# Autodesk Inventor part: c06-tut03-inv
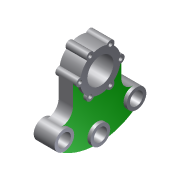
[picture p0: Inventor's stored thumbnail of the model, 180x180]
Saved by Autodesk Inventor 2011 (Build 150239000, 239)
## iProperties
Created: 2010-03
Part Number: c06-tut03-inv
Document SubType Name: Modeling
Designer: CADSoft
Density: 1 g/cm^3
Author: CADSoft
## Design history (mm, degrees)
sketch "Sketch1"
  geometry: 1 further point
sketch "Sketch2"
  geometry: L1 (-37, 0)-(-37, -31.635); L2 (37, 0)-(37, -31.635); A1 r 100 centre (0, 0) between (-64.945, -76.041) and (64.945, -76.041); A2 r 18 centre (-55, -31.635) between (-55.111, -49.635) and (-37, -31.635); A3 r 15 centre (-55.203, -64.635) between (-55.111, -49.635) and (-64.945, -76.041); A4 r 18 centre (55, -31.635) between (37, -31.635) and (55.111, -49.635); A5 r 15 centre (55.203, -64.635) between (64.945, -76.041) and (55.111, -49.635); A6 r 31 centre (0, 0) between (30.419, 5.972) and (-30.419, 5.972); A7 r 6 centre (31, 0) between (37, 0) and (30.419, 5.972); A8 r 6 centre (-31, 0) between (-30.419, 5.972) and (-37, 0); 1 further point
  constraints: 18 point on circle, 8 centre point, 8 tangent, 4 end point, 3 equal radius, 2 coincident, 2 horizontal alignment, 2 vertical, 1 parallel, 1 point on line
  dimensions: "d0" = 100 radius of A1; "d4" = 15 radius of A5; "d5" = 18 radius of A4; "d7" = 81 deg dimension on point (0, 0) A5.centre A3.centre; "d16" = 31 radius of A6; "d17" = 6 radius of A8
extrude "Extrusion1" new body sketch "Sketch2" stored distance "d8" = 22; taper "d9" = 0 deg
sketch "Sketch5"
  geometry: A1 r 6 centre (-31, 0) between (-30.419, 5.972) and (-30.419, -5.972); A2 r 6 centre (-31, 0) between (-30.419, 5.972) and (-37, 0) reference; A3 r 6 centre (-15.5, -26.847) between (-20.381, -23.358) and (-10.038, -29.33); A4 r 6 centre (15.5, -26.847) between (10.038, -29.33) and (20.381, -23.358); A5 r 6 centre (31, 0) between (30.419, -5.972) and (30.419, 5.972); A6 r 6 centre (15.5, 26.847) between (20.381, 23.358) and (10.038, 29.33); A7 r 6 centre (-15.5, 26.847) between (-10.038, 29.33) and (-20.381, 23.358); A8 r 31 centre (0, 0) between (10.038, 29.33) and (-10.038, 29.33); A9 r 31 centre (0, 0) between (30.419, 5.972) and (20.381, 23.358); A10 r 31 centre (0, 0) between (20.381, -23.358) and (30.419, -5.972); A11 r 31 centre (0, 0) between (-20.381, 23.358) and (-30.419, 5.972); A12 r 31 centre (0, 0) between (-30.419, -5.972) and (-20.381, -23.358); A13 r 31 centre (0, 0) between (-10.038, -29.33) and (10.038, -29.33); 1 further point
  constraints: 26 point on circle, 12 centre point, 1 coincident, 1 concentric
extrude "Extrusion2" join sketch "Sketch5" stored distance "d19" = 32; taper "d20" = 0 deg
hole "Hole1" diameter "d23" = 6; stored, may be unused: countersink angle "d27" = 90 deg, drill point angle "d29" = 118 deg; dims "d21" = 10, "d22" = 10, "d24" = 6, "d25" = 4, "d26" = 2, "d28" = 8
pattern_circular "Circular Pattern1" dims angle "d31" = 360 deg
sketch "Sketch6"
  geometry: C1 r 15 at (-55.203, -64.635); A1 r 15 centre (-55.203, -64.635) between (-55.111, -49.635) and (-64.945, -76.041) reference; 1 further point
  constraints: 1 centre point, 1 concentric
  dimensions: "d33" = 30 diameter of C1
extrude "Extrusion3" join sketch "Sketch6" stored distance "d34" = 32; taper "d35" = 0 deg
hole "Hole2" diameter "d38" = 20; stored, may be unused: countersink angle "d42" = 90 deg, drill point angle "d44" = 118 deg; dims "d36" = 10, "d37" = 10, "d39" = 6, "d40" = 4, "d41" = 2, "d43" = 8
pattern_circular "Circular Pattern2" dims angle "d46" = 81 deg
hole "Hole3" diameter "d50" = 40; stored, may be unused: countersink angle "d54" = 90 deg, drill point angle "d56" = 118 deg; dims "d48" = 10, "d49" = 10, "d51" = 6, "d52" = 4, "d53" = 2, "d55" = 8
body "Solid1"
other parameters: "d18" = 62
